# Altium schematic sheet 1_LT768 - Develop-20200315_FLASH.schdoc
size 762 x 261 mm
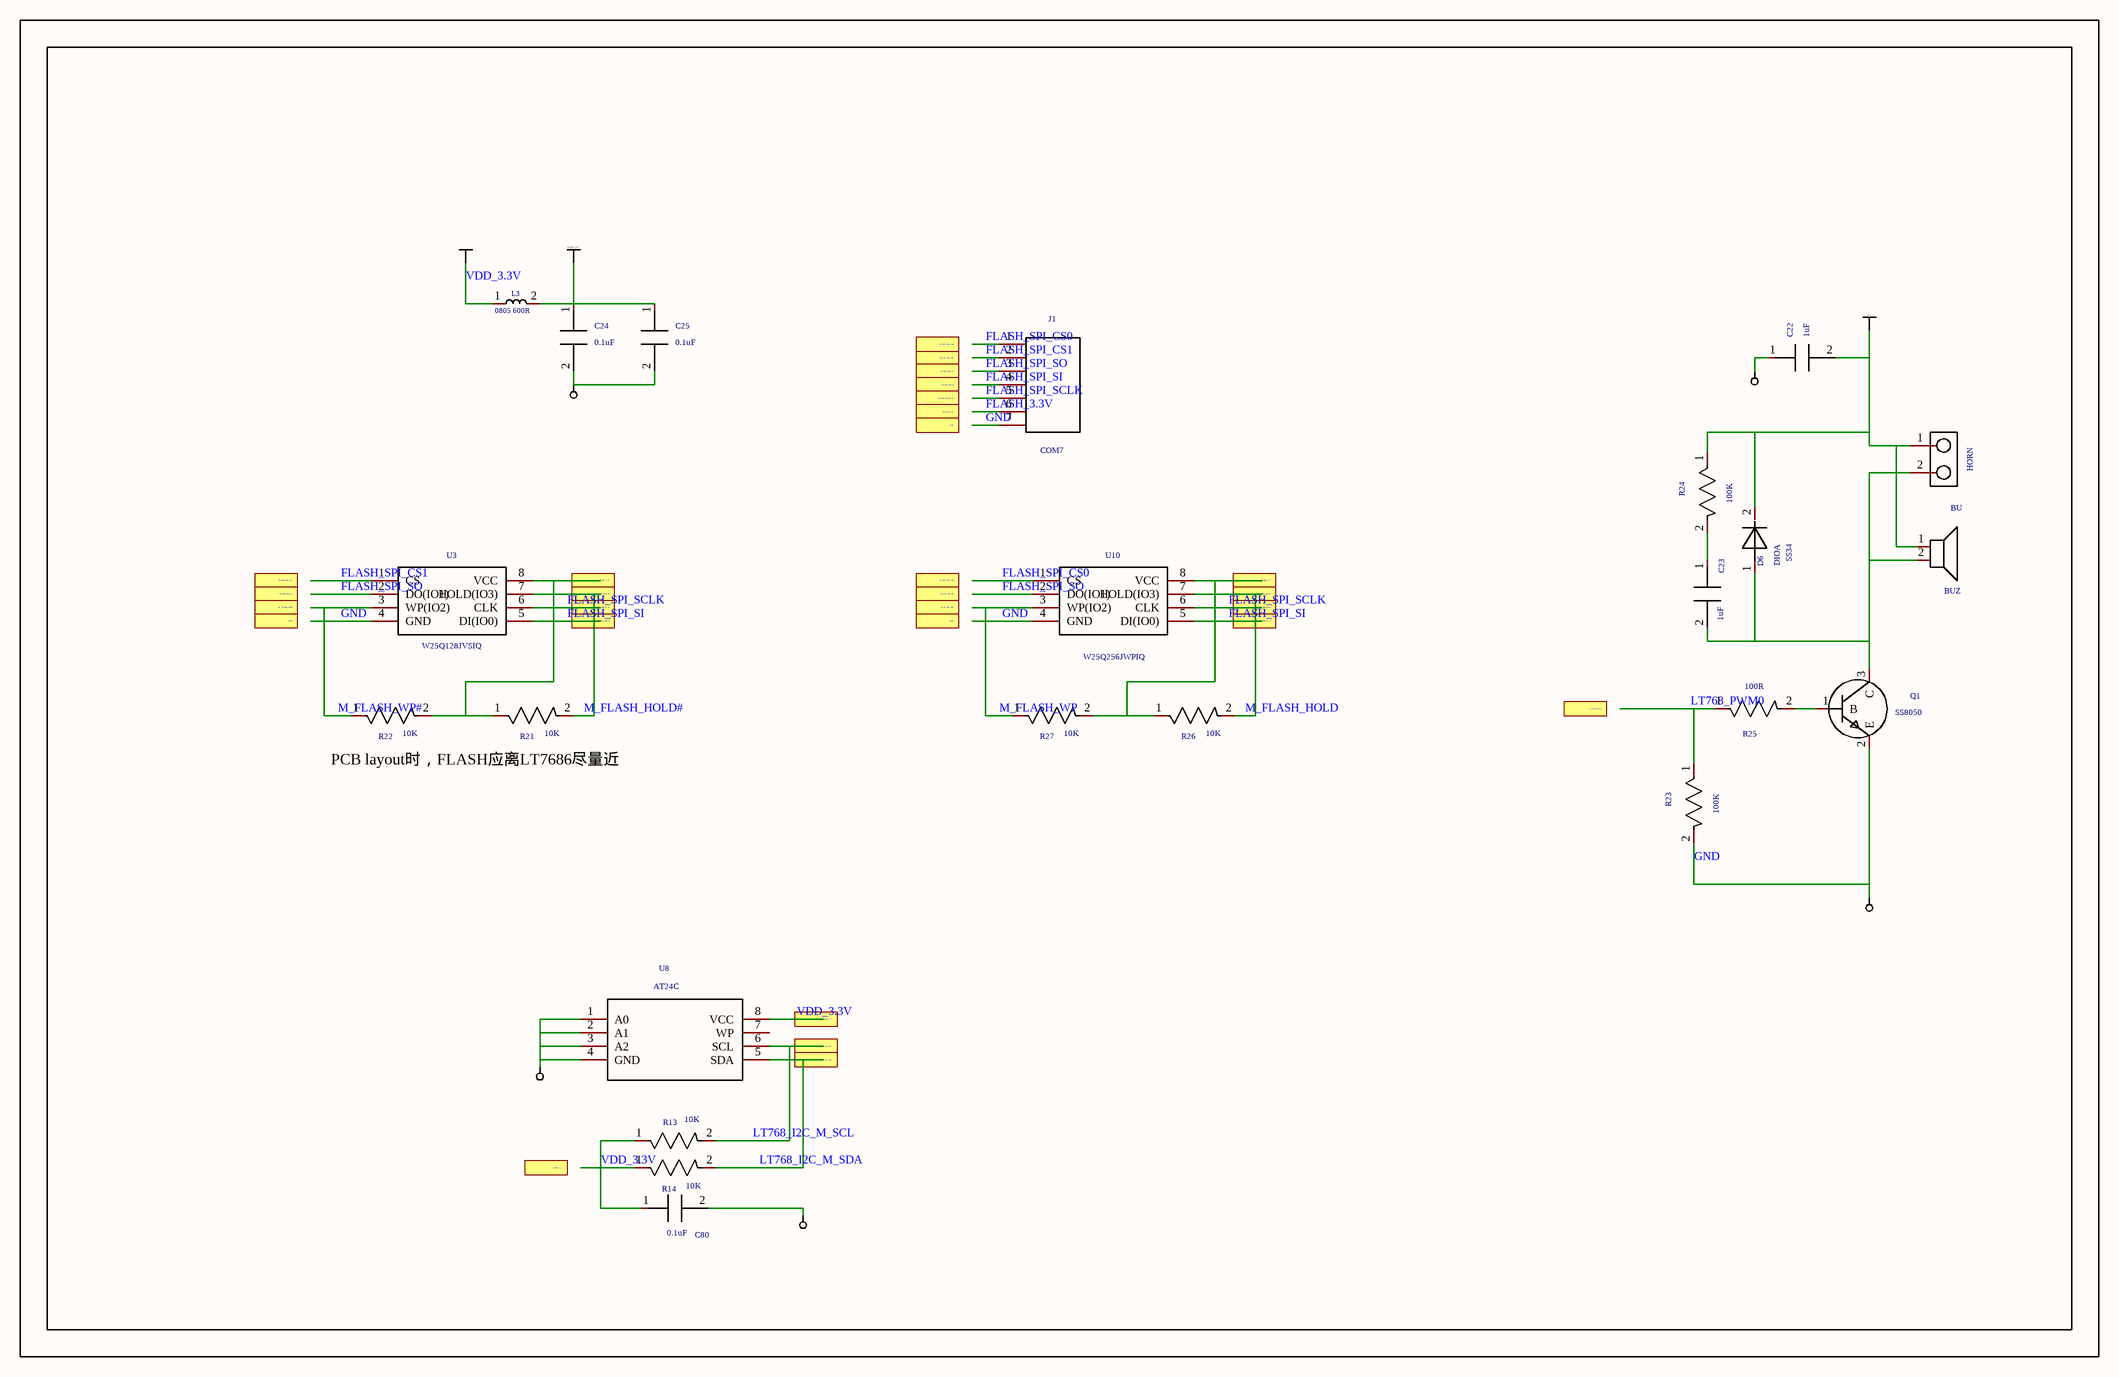
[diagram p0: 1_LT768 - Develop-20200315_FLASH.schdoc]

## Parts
BU  BUZ
C22  1uF
C23  1uF
C24  0.1uF
C25  0.1uF
C80  0.1uF
D6  SS34
HORN  COM2  (value not drawn)
J1  COM7  [COM7]
L3  0805 600R
Q1  value SS8050  (hidden comment: NPN_B1E2C3)
R13  10K
R14  10K
R21  10K
R22  10K
R23  100K
R24  100K
R25  100R
R26  10K
R27  10K
U3  W25Q128JVSIQ
U8  AT24C
U10  value W25Q256JWPIQ  (hidden comment: W25Q128JVSIQ)

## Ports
FLASH_3.3V (in), FLASH_SPI_CS0 (in), FLASH_SPI_CS1 (in), FLASH_SPI_SCLK (in), FLASH_SPI_SI (in), FLASH_SPI_SO (in), GND (in), LT768_I2C_M_SCL (in), LT768_I2C_M_SDA (in), LT768_PWM0 (in), M_FLASH_HOLD (in), M_FLASH_HOLD# (in), M_FLASH_WP (in), M_FLASH_WP# (in), VDD_3.3V (in)

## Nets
+5V: BU.1 C22.2 D6.2 HORN.1 R24.1
FLASH_3.3V: C24.1 C25.1 J1.6 L3.2
GND: C22.1 C24.2 C25.2 C80.2 J1.7 Q1.2(E) R23.2 U3.4(GND) U8.1(A0) U8.2(A1) U8.3(A2) U8.4(GND) U10.4(GND)
VDD_3.3V: C80.1 L3.1 R13.1 R14.1 U8.8(VCC) ; port VDD_3.3V
FLASH_3.3V: R21.1 R22.2 R26.1 R27.2 U3.8(VCC) U10.8(VCC) ; port FLASH_3.3V  [a separate net that carries the same name]
FLASH_SPI_CS0: J1.1 U10.1(CS)
FLASH_SPI_CS1: J1.2 U3.1(CS)
FLASH_SPI_SCLK: J1.5 U3.6(CLK) U10.6(CLK) ; port FLASH_SPI_SCLK
FLASH_SPI_SI: J1.4 U3.5(DI(IO0)) U10.5(DI(IO0)) ; port FLASH_SPI_SI
FLASH_SPI_SO: J1.3 U3.2(DO(IO1)) U10.2(DO(IO1))
LT768_I2C_M_SCL: R13.2 U8.6(SCL) ; port LT768_I2C_M_SCL
LT768_I2C_M_SDA: R14.2 U8.5(SDA) ; port LT768_I2C_M_SDA
LT768_PWM0: R23.1 R25.1
M_FLASH_HOLD: R26.2 U10.7(HOLD(IO3)) ; port M_FLASH_HOLD
M_FLASH_HOLD#: R21.2 U3.7(HOLD(IO3)) ; port M_FLASH_HOLD#
M_FLASH_WP: R27.1 U10.3(WP(IO2))
M_FLASH_WP#: R22.1 U3.3(WP(IO2))
NetBU_2: BU.2 C23.2 D6.1 HORN.2 Q1.3(C)
NetC23_1: C23.1 R24.2
NetQ1_1: Q1.1(B) R25.2

Not connected (* = marked no-connect by the designer): U8 7(WP)

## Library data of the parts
BU = BUZ: Buzzer; Add into BOM: yes; PCB DECAL: BUZZER/9MM
C22-C25 C80 = CAP0603: Capacitor; PART DESC: CERAMIC CAP.0.1UF/50V +/-20% 0603; PART NO: 014104BZ2503; PART NUMBER: 022-109600310-00; Symbol: CAP; Add into BOM: yes; _: 0.0103; PCB DECAL: C0603
D6 = DIOA: Diode; Add into BOM: yes; PCB DECAL: DO-214
HORN = COM2: Header; Symbol: CON2_PIN; Add into BOM: yes; PCB DECAL: JACK/2.54MM
J1 = COM7: Header; Add into BOM: yes
L3 = 47UH-CHOKE: BEAD; PART DESC: COIL 47uH-CHOKE; PART NUMBER: 037-001000001-00; Symbol: FB220; Add into BOM: yes; PCB DECAL: L0805
Q1 = NPN_B1E2C3: NPN transistor; Manufacturer: KEC; Add into BOM: yes; Source_Path: O:\CAPTURE_LIB\TECSENDLIB.OLB; Layout_PCB_Footprint: SOT-23; FPLIST: SOT_23,SOT_23_S,SOT_23_M,SOT_23_S_M; Simulation_Model: Q; U/P: 0; PCB DECAL: SOT-23-1
R13 R14 R21-R27 = RES: Resistance; Symbol: RESZ-V; Add into BOM: yes; PCB DECAL: R0603
U3 = W25Q128JVSIQ: IC; Symbol: SOP8A; Add into BOM: yes; PCB DECAL: SOP8-208
U8 = AT24C: IC; Part_Type: EEPROM; Symbol: M24C04; Add into BOM: yes; PCB DECAL: SO8-OPT
U10 = W25Q128JVSIQ: IC; Symbol: SOP8A; Add into BOM: yes; PCB DECAL: WSON8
